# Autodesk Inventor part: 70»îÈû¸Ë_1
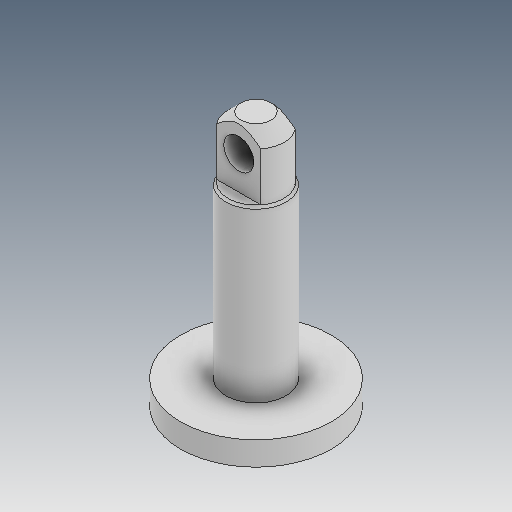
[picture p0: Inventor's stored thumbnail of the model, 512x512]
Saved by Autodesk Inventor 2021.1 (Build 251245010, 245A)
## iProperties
Created: 2019-04
Part Number: 70»îÈû¸Ë_1
Material: Ogólny
Document SubType Name: Modeling
Designer: user
Density: 1 g/cm^3
Appearance: Domyślna
Author: user
Revision Number: ÈÎºÎ
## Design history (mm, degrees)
feature "ÊäÈë1"
node "Bryła1"
